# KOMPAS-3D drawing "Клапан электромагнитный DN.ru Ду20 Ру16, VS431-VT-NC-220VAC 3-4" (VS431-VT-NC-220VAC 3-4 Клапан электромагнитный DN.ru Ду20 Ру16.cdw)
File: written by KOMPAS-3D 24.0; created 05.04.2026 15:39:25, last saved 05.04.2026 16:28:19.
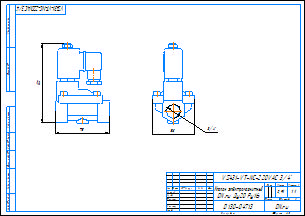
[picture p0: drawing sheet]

Document properties: c3d_UniqueCompID: ef56311e-7521-43dc-8291-0e6108b3d81d; Автор: artio; Класс точности: c; Знак неуказанной шероховатости: Шероховатость не задана; Рассекать на разрезах: Да; Автор: artio; Форматы листов документа: A3; Полное имя файла: VS431-VT-NC-220VAC 3-4 Клапан электромагнитный DN.ru Ду20 Ру16.m3d; Масса: 0.907; Наименование: Клапан электромагнитный DN.ru Ду20 Ру16; Количество листов документа: 1; Примечание: D130-04713

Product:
- Body: Тело 1  | qty 1
    Масса: 1.198355
- Part/product: Клапан электромагнитный DN.ru Ду20 Ру16  | designation VS431-VT-NC-220VAC 3-4
    Масса: 0.907
    Раздел спецификации: Прочие изделия
    Примечание: D130-04713
    additional columns: ef56311e-7521-43dc-8291-0e6108b3d81d; artio; c; Шероховатость не задана; Да

Views: Вид 1, Спереди, Проекционный вид 2
Referenced files in C:\Users\artio\OneDrive\Рабочий стол\Клапан электромагнитный DN.ru\VS431\VS431-ET-NC\: VS431-ET-NC-220VAC 3-4 Клапан электромагнитный DN.ru Ду20 Ру16.m3d
Referenced files in C:\Users\artio\OneDrive\Рабочий стол\Клапан электромагнитный DN.ru\VS431\VS431-VT-NC\: VS431-VT-NC-220VAC 3-4 Клапан электромагнитный DN.ru Ду20 Ру16.m3d
Referenced files in C:\Users\artio\OneDrive\Рабочий стол\Клапан электромагнитный DN.ru\VS431\VS431-NT-NC\: VS431-NT-NC-220VAC 3-4 Клапан электромагнитный DN.ru Ду20 Ру16.cdw
Referenced files in C:\Users\artio\OneDrive\Рабочий стол\Клапан электромагнитный DN.ru\VS431\VS431-VT-NC\VS431-VT-NC-220VAC\Ду20\: VS431-VT-NC-220VAC 3-4 Клапан электромагнитный DN.ru Ду20 Ру16.m3d
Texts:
  VS431-VT-NC-220VAC 3-4
  Клапан электромагнитный
  DN.ru Ду20 Ру16
  VS431-VT-NC-220VAC 3/4"
  VS431-VT-NC-220VAC 3/4"-
  Клапан электромагнитный DN.ru Ду20 Ру16
  VS431-VT-NC-220VAC 3-4 Клапан электромагнитный DN.ru Ду20 Ру16
Dimensions and other numbers on the sheet: 0; 3; 2; 4; 58; 3/4"; 75; 110; 1:1; 1; 0,91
